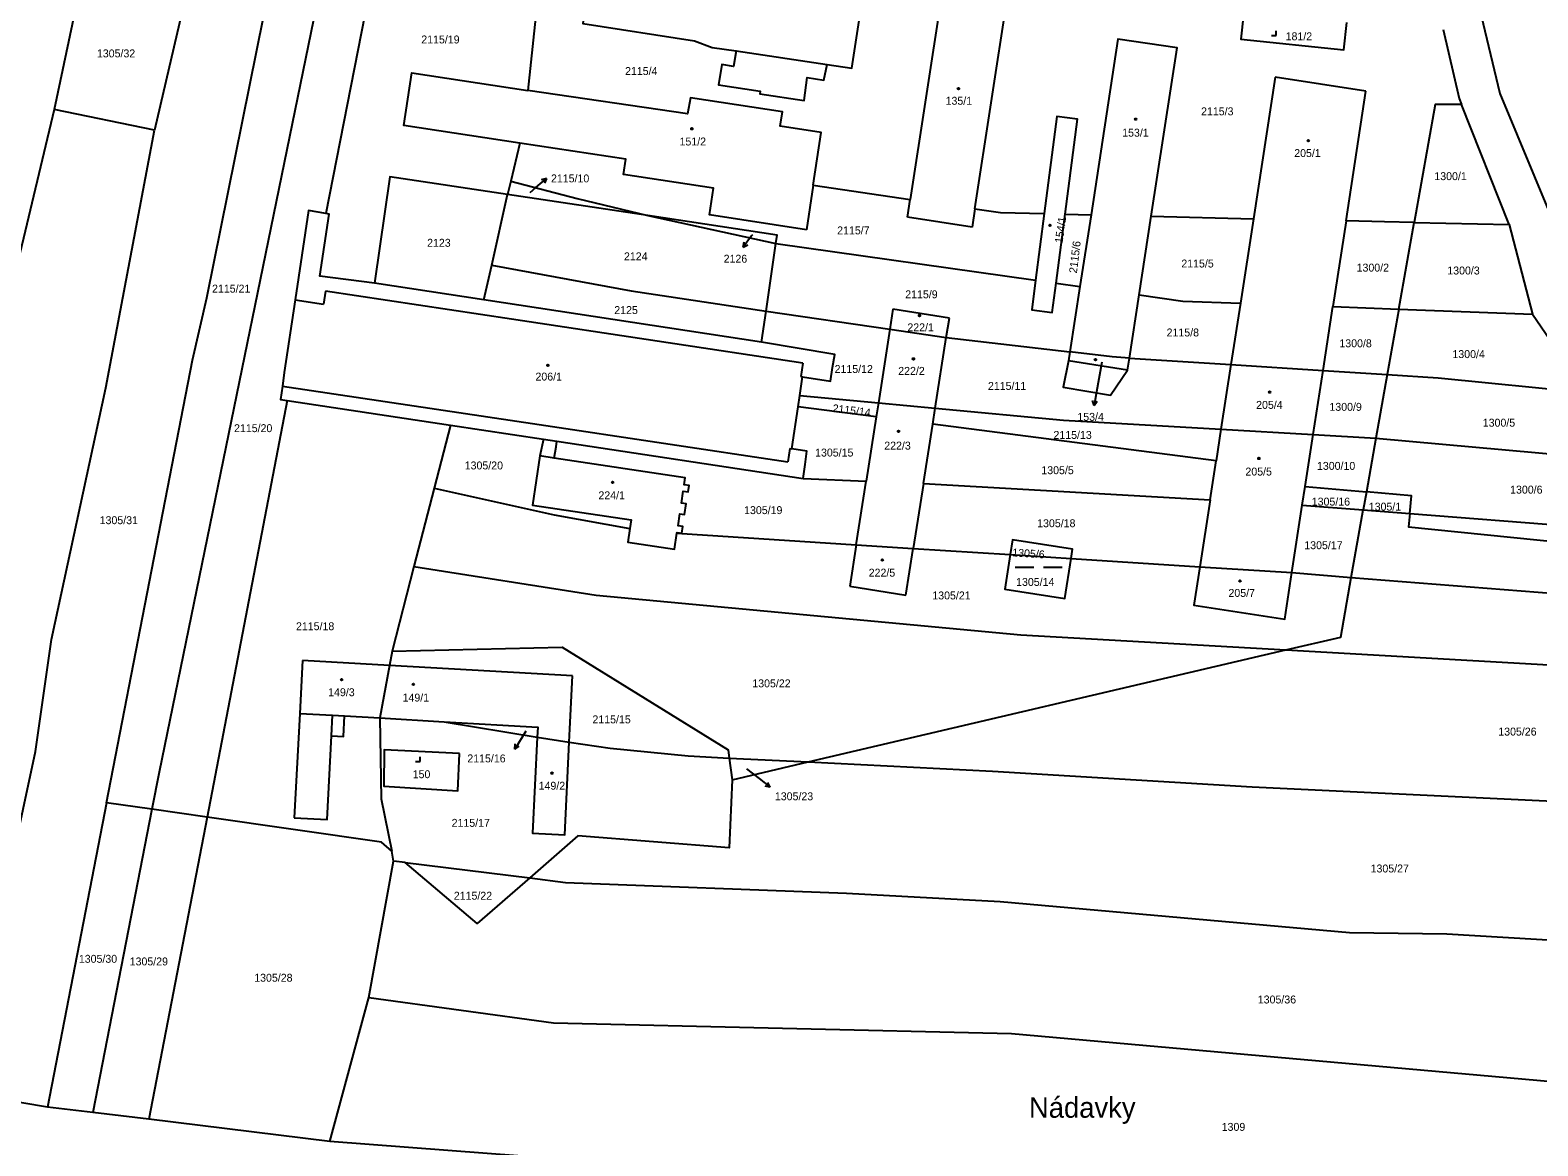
# Model space of a CAD drawing. Extents: x -755528 to -748832, y -1118122 to -1111095.
# Drawn here: x -750683.1 to -750359.5, y -1114035.1 to -1113795.7 of the extents above; entities that cross this region are included whole.
import ezdxf

# ---------------------------------------------------------------- set-up
doc = ezdxf.new("R2010")
doc.units = 0
for name, color, linetype in [('DZ_DO_ostatní', 7, 'Continuous'), ('DZ_DO_PUPFL', 7, 'Continuous'), ('DZ_NAD_ZPF', 7, 'Continuous'), ('legenda barvy', 7, 'Continuous'), ('legenda_text', 7, 'Continuous'), ('TZ_UMVŽST', 7, 'Continuous')]:
    doc.layers.add(name, color=color, linetype=linetype)

msp = doc.modelspace()

# ---------------------------------------------------------------- linework, layer by layer
at = {"layer": 'DZ_DO_ostatní'}
for p, q in [((-750531.57, -1113800.11), (-750512.05, -1113803)), ((-750626.22, -1113853.56), (-750620.16, -1113854.48)), ((-750619.74, -1113851.7), (-750620.16, -1113854.48)), ((-750579.79, -1113857.69), (-750619.74, -1113851.7)), ((-750517.27, -1113867.15), (-750579.79, -1113857.69)), ((-750517.27, -1113867.15), (-750517.71, -1113870)), ((-750447.58, -1113868.63), (-750460.26, -1113866.64)), ((-750517.71, -1113870), (-750517.31, -1113870.06)), ((-750628.95, -1113872.04), (-750573.89, -1113880.32)), ((-750573.89, -1113880.32), (-750520.46, -1113888.32)), ((-750520.05, -1113885.48), (-750520.46, -1113888.32)), ((-750520.05, -1113885.48), (-750519.64, -1113885.55)), ((-750570.61, -1113887.56), (-750573.73, -1113887.05)), ((-750625.24, -1113942.31), (-750618.2, -1113942.71)), ((-750618.43, -1113947.13), (-750618.2, -1113942.71)), ((-750618.2, -1113942.71), (-750615.6, -1113942.86))]:
    msp.add_line(p, q, dxfattribs=at)
at = {"layer": 'DZ_NAD_ZPF'}
for p, q in [((-750605.82, -1113764.21), (-750619.61, -1113835.03)), ((-750572.98, -1113776.85), (-750576.28, -1113808.6)), ((-750671.89, -1113783.99), (-750677.92, -1113812.71)), ((-750649.83, -1113788.82), (-750656.44, -1113817.12)), ((-750487.35, -1113787.31), (-750494.25, -1113831.98)), ((-750480.33, -1113834), (-750473.32, -1113788.44)), ((-750415.89, -1113805.74), (-750420.58, -1113836.13)), ((-750396.42, -1113808.74), (-750415.89, -1113805.74)), ((-750400.7, -1113836.62), (-750396.42, -1113808.74)), ((-750365.72, -1113837.4), (-750375.89, -1113811.64)), ((-750656.44, -1113817.12), (-750677.92, -1113812.71)), ((-750578, -1113819.92), (-750579.97, -1113828.05)), ((-750579.97, -1113828.05), (-750580.67, -1113830.94)), ((-750584.04, -1113846.07), (-750580.67, -1113830.94)), ((-750550.52, -1113835.47), (-750580.67, -1113830.94)), ((-750515.05, -1113828.96), (-750516.48, -1113838.52)), ((-750515.05, -1113828.96), (-750494.25, -1113831.98)), ((-750494.84, -1113835.77), (-750494.25, -1113831.98)), ((-750480.33, -1113834), (-750480.93, -1113837.93)), ((-750465.45, -1113835.03), (-750467.31, -1113849.32)), ((-750550.52, -1113835.47), (-750523.05, -1113841.42)), ((-750480.93, -1113837.93), (-750494.84, -1113835.77)), ((-750462.92, -1113849.94), (-750461, -1113835.14)), ((-750461, -1113835.14), (-750455.43, -1113835.28)), ((-750455.43, -1113835.28), (-750457.8, -1113850.67)), ((-750445.09, -1113852.47), (-750442.49, -1113835.6)), ((-750442.49, -1113835.6), (-750420.58, -1113836.13)), ((-750420.58, -1113836.13), (-750423.37, -1113854.26)), ((-750400.7, -1113836.62), (-750403.53, -1113855)), ((-750389.35, -1113855.53), (-750386.06, -1113836.96)), ((-750386.06, -1113836.96), (-750365.72, -1113837.4)), ((-750365.72, -1113837.4), (-750360.65, -1113856.6)), ((-750525.16, -1113855.97), (-750523.05, -1113841.42)), ((-750523.05, -1113841.42), (-750467.31, -1113849.32)), ((-750585.71, -1113853.56), (-750584.04, -1113846.07)), ((-750585.71, -1113853.56), (-750609.23, -1113849.98)), ((-750462.92, -1113849.94), (-750457.8, -1113850.67)), ((-750457.8, -1113850.67), (-750459.97, -1113864.73)), ((-750526.11, -1113862.62), (-750585.71, -1113853.56)), ((-750447.18, -1113866.03), (-750445.09, -1113852.47)), ((-750423.37, -1113854.26), (-750425.4, -1113867.42)), ((-750526.11, -1113862.62), (-750525.16, -1113855.97)), ((-750525.16, -1113855.97), (-750498.6, -1113859.85)), ((-750497.93, -1113855.58), (-750498.6, -1113859.85)), ((-750485.83, -1113857.5), (-750497.93, -1113855.58)), ((-750486.48, -1113861.61), (-750485.83, -1113857.5)), ((-750405.63, -1113868.69), (-750403.53, -1113855)), ((-750403.53, -1113855), (-750389.35, -1113855.53)), ((-750389.35, -1113855.53), (-750391.84, -1113869.57)), ((-750389.35, -1113855.53), (-750360.65, -1113856.6)), ((-750360.65, -1113856.6), (-750349.25, -1113873.44)), ((-750498.6, -1113859.85), (-750501.06, -1113875.64)), ((-750498.6, -1113859.85), (-750486.48, -1113861.61)), ((-750488.86, -1113876.79), (-750486.48, -1113861.61)), ((-750486.48, -1113861.61), (-750459.97, -1113864.73)), ((-750447.18, -1113866.03), (-750425.4, -1113867.42)), ((-750425.4, -1113867.42), (-750427.54, -1113881.32)), ((-750425.4, -1113867.42), (-750405.63, -1113868.69)), ((-750407.75, -1113882.46), (-750405.63, -1113868.69)), ((-750405.63, -1113868.69), (-750391.84, -1113869.57)), ((-750391.84, -1113869.57), (-750394.27, -1113883.24)), ((-750627.92, -1113875.15), (-750645.14, -1113964.57)), ((-750627.92, -1113875.15), (-750592.92, -1113880.42)), ((-750518.28, -1113876.48), (-750517.91, -1113874.06)), ((-750501.53, -1113878.65), (-750518.28, -1113876.48)), ((-750517.91, -1113874.06), (-750501.06, -1113875.64)), ((-750501.06, -1113875.64), (-750501.53, -1113878.65)), ((-750501.06, -1113875.64), (-750488.86, -1113876.79)), ((-750489.4, -1113880.22), (-750488.86, -1113876.79)), ((-750501.53, -1113878.65), (-750503.69, -1113892.45)), ((-750491.41, -1113892.98), (-750489.4, -1113880.22)), ((-750428.58, -1113888.08), (-750489.4, -1113880.22)), ((-750592.92, -1113880.42), (-750596.4, -1113893.95)), ((-750592.92, -1113880.42), (-750572.92, -1113883.43)), ((-750572.92, -1113883.43), (-750570.04, -1113883.89)), ((-750427.54, -1113881.32), (-750428.58, -1113888.08)), ((-750427.54, -1113881.32), (-750407.75, -1113882.46)), ((-750409.46, -1113893.59), (-750407.75, -1113882.46)), ((-750407.75, -1113882.46), (-750394.27, -1113883.24)), ((-750394.27, -1113883.24), (-750396.31, -1113894.76)), ((-750394.27, -1113883.24), (-750331.5, -1113888.93)), ((-750570.04, -1113883.89), (-750517.22, -1113891.86)), ((-750429.87, -1113896.48), (-750428.58, -1113888.08)), ((-750517.22, -1113891.86), (-750503.69, -1113892.45)), ((-750505.82, -1113906.11), (-750503.69, -1113892.45)), ((-750491.41, -1113892.98), (-750493.6, -1113906.89)), ((-750491.41, -1113892.98), (-750429.87, -1113896.48)), ((-750596.4, -1113893.95), (-750600.73, -1113910.8)), ((-750429.87, -1113896.48), (-750432.08, -1113910.83)), ((-750410.08, -1113897.6), (-750409.46, -1113893.59)), ((-750409.46, -1113893.59), (-750396.31, -1113894.76)), ((-750396.31, -1113894.76), (-750396.99, -1113898.61)), ((-750412.3, -1113912.1), (-750410.08, -1113897.6)), ((-750410.08, -1113897.6), (-750396.99, -1113898.61)), ((-750399.57, -1113913.11), (-750396.99, -1113898.61)), ((-750396.99, -1113898.61), (-750386.99, -1113899.39)), ((-750386.99, -1113899.39), (-750309.59, -1113905.41)), ((-750544.28, -1113903.64), (-750505.82, -1113906.11)), ((-750505.82, -1113906.11), (-750507.21, -1113915.01)), ((-750505.82, -1113906.11), (-750493.6, -1113906.89)), ((-750495.17, -1113916.92), (-750493.6, -1113906.89)), ((-750493.6, -1113906.89), (-750472.79, -1113908.22)), ((-750472.79, -1113908.22), (-750459.71, -1113909.06)), ((-750459.71, -1113909.06), (-750432.08, -1113910.83)), ((-750600.73, -1113910.8), (-750605.39, -1113928.92)), ((-750432.08, -1113910.83), (-750412.3, -1113912.1)), ((-750412.3, -1113912.1), (-750399.57, -1113913.11)), ((-750507.21, -1113915.01), (-750495.17, -1113916.92)), ((-750399.57, -1113913.11), (-750290.98, -1113921.75)), ((-750516.14, -1113952.73), (-750413.63, -1113928.68)), ((-750413.63, -1113928.68), (-750275.6, -1113936.54)), ((-750605.96, -1113932), (-750624.64, -1113930.95)), ((-750605.96, -1113932), (-750608.04, -1113943.29)), ((-750605.39, -1113928.92), (-750605.96, -1113932)), ((-750566.67, -1113934.23), (-750605.96, -1113932)), ((-750567.26, -1113945.63), (-750566.67, -1113934.23)), ((-750608.04, -1113943.29), (-750594.23, -1113944.09)), ((-750594.23, -1113944.09), (-750574.26, -1113947.42)), ((-750574.26, -1113947.42), (-750567.4, -1113948.45)), ((-750567.4, -1113948.45), (-750567.26, -1113945.63)), ((-750533.06, -1113951.88), (-750516.14, -1113952.73)), ((-750533.06, -1113951.88), (-750532.46, -1113956.56)), ((-750532.46, -1113956.56), (-750516.14, -1113952.73)), ((-750666.69, -1113961.47), (-750679.36, -1114026.8)), ((-750656.98, -1113962.87), (-750669.61, -1114027.94)), ((-750656.98, -1113962.87), (-750666.69, -1113961.47)), ((-750645.14, -1113964.57), (-750656.98, -1113962.87)), ((-750645.14, -1113964.57), (-750657.61, -1114029.36)), ((-750610.4, -1114003.29), (-750605.15, -1113973.99)), ((-750605.15, -1113973.99), (-750605.46, -1113971.88)), ((-750602.6, -1113974.3), (-750605.15, -1113973.99)), ((-750602.6, -1113974.3), (-750575.88, -1113977.58)), ((-750618.81, -1114034.16), (-750610.4, -1114003.29)), ((-750679.36, -1114026.8), (-750697.69, -1114023.72)), ((-750669.61, -1114027.94), (-750679.36, -1114026.8)), ((-750657.61, -1114029.36), (-750669.61, -1114027.94)), ((-750618.81, -1114034.16), (-750657.61, -1114029.36))]:
    msp.add_line(p, q, dxfattribs=at)
for points in [[(-750394.18, -1113687.07), (-750374.25, -1113712.84), (-750364.39, -1113734.2), (-750362.92, -1113755.97), (-750369.18, -1113776.02), (-750371.71, -1113792.51), (-750367.7, -1113809.24), (-750356.56, -1113836.11), (-750350.79, -1113846.38)], [(-750616.02, -1113762.71), (-750655.44, -1113954.92), (-750656.98, -1113962.87)], [(-750545.29, -1113783.44), (-750562.36, -1113780.95), (-750564.5, -1113794.22), (-750540.53, -1113797.95), (-750536.71, -1113799.35), (-750531.57, -1113800.11), (-750532.13, -1113803.44), (-750534.69, -1113803.06), (-750535.35, -1113807.43), (-750526.44, -1113808.76), (-750526.5, -1113809.3), (-750516.99, -1113810.76), (-750516.33, -1113805.85), (-750512.74, -1113806.39), (-750512.05, -1113803), (-750506.74, -1113803.79), (-750504.44, -1113788.89), (-750511.58, -1113787.57), (-750511.24, -1113785.44)], [(-750666.69, -1113961.47), (-750648.27, -1113866.49), (-750645.15, -1113853.14), (-750632.98, -1113792.5)], [(-750422.71, -1113792.34), (-750423.28, -1113797.57), (-750401.17, -1113799.91), (-750400.54, -1113793.99)], [(-750379.85, -1113795.53), (-750376.41, -1113810.33), (-750375.89, -1113811.64)], [(-750442.49, -1113835.6), (-750436.94, -1113799.49), (-750449.64, -1113797.58), (-750455.43, -1113835.28)], [(-750578, -1113819.92), (-750602.88, -1113816.13), (-750601.2, -1113804.85), (-750576.28, -1113808.6)], [(-750515.05, -1113828.96), (-750513.35, -1113817.62), (-750522.12, -1113816.26), (-750521.67, -1113813.19), (-750541.39, -1113810.16), (-750541.99, -1113813.59), (-750576.28, -1113808.6)], [(-750375.89, -1113811.64), (-750381.57, -1113811.64), (-750386.06, -1113836.96)], [(-750677.92, -1113812.71), (-750688.59, -1113857.37), (-750702.1, -1113930.36), (-750719.33, -1114017.54)], [(-750461, -1113835.14), (-750458.36, -1113814.78), (-750462.75, -1113814.21), (-750465.45, -1113835.03)], [(-750697.69, -1114023.72), (-750681.93, -1113950.45), (-750678.53, -1113926.42), (-750666.87, -1113872.44), (-750656.44, -1113817.12)], [(-750516.48, -1113838.52), (-750537.28, -1113835.31), (-750536.46, -1113829.59), (-750555.75, -1113826.67), (-750555.25, -1113823.35), (-750578, -1113819.92)], [(-750580.67, -1113830.94), (-750605.88, -1113827.15), (-750609.23, -1113849.98)], [(-750579.97, -1113828.05), (-750565.67, -1113831.82), (-750550.52, -1113835.47)], [(-750619.61, -1113835.03), (-750623.39, -1113834.4), (-750626.22, -1113853.56), (-750628.57, -1113869.14), (-750628.95, -1113872.04), (-750629.4, -1113874.92), (-750627.92, -1113875.15)], [(-750609.23, -1113849.98), (-750620.95, -1113848.49), (-750618.94, -1113835.14), (-750619.61, -1113835.03)], [(-750480.33, -1113834), (-750474.83, -1113834.8), (-750465.45, -1113835.03)], [(-750523.05, -1113841.42), (-750522.8, -1113839.63), (-750550.52, -1113835.47)], [(-750386.06, -1113836.96), (-750392.45, -1113836.82), (-750400.7, -1113836.62)], [(-750584.04, -1113846.07), (-750554.14, -1113851.63), (-750525.16, -1113855.97)], [(-750467.31, -1113849.32), (-750468.13, -1113855.68), (-750463.74, -1113856.25), (-750462.92, -1113849.94)], [(-750445.09, -1113852.47), (-750435.75, -1113853.8), (-750423.37, -1113854.26)], [(-750517.91, -1113874.06), (-750517.31, -1113870.06), (-750511.37, -1113870.98), (-750510.89, -1113868.04), (-750510.44, -1113865.31), (-750526.11, -1113862.62)], [(-750459.97, -1113864.73), (-750460.26, -1113866.64), (-750461.43, -1113872.32), (-750451.23, -1113874.02), (-750447.58, -1113868.63), (-750447.18, -1113866.03)], [(-750447.18, -1113866.03), (-750450.92, -1113865.79), (-750459.97, -1113864.73)], [(-750391.84, -1113869.57), (-750380.96, -1113870.27), (-750349.25, -1113873.44)], [(-750517.22, -1113891.86), (-750516.79, -1113888.85), (-750516.44, -1113886), (-750519.64, -1113885.55), (-750518.28, -1113876.48)], [(-750488.86, -1113876.79), (-750461.36, -1113879.38), (-750427.54, -1113881.32)], [(-750572.92, -1113883.43), (-750573.73, -1113887.05), (-750575.3, -1113897.58), (-750554.12, -1113900.77), (-750554.4, -1113902.61)], [(-750544.28, -1113903.64), (-750544.26, -1113903.49), (-750543.27, -1113903.64), (-750543.06, -1113902.22), (-750544.05, -1113902.08), (-750543.66, -1113899.48), (-750542.67, -1113899.62), (-750542.3, -1113897.31), (-750543.31, -1113897.16), (-750542.92, -1113894.58), (-750541.87, -1113894.74), (-750541.68, -1113893.39), (-750542.73, -1113893.25), (-750542.5, -1113891.77), (-750570.61, -1113887.56), (-750570.22, -1113885.09), (-750570.04, -1113883.89)], [(-750596.4, -1113893.95), (-750570.62, -1113899.71), (-750554.4, -1113902.61)], [(-750386.99, -1113899.39), (-750386.63, -1113895.63), (-750396.31, -1113894.76)], [(-750386.99, -1113899.39), (-750387.26, -1113902.24), (-750303.26, -1113910.79)], [(-750554.4, -1113902.61), (-750554.83, -1113905.55), (-750544.83, -1113907.07), (-750544.28, -1113903.64)], [(-750459.71, -1113909.06), (-750459.4, -1113907.06), (-750472.31, -1113905.08), (-750472.79, -1113908.22)], [(-750472.79, -1113908.22), (-750473.93, -1113915.67), (-750461.02, -1113917.65), (-750459.71, -1113909.06)], [(-750600.73, -1113910.8), (-750561.61, -1113916.9), (-750470.46, -1113925.45), (-750413.63, -1113928.68)], [(-750432.08, -1113910.83), (-750433.35, -1113919.06), (-750413.84, -1113922.11), (-750412.3, -1113912.1)], [(-750413.63, -1113928.68), (-750401.84, -1113925.92), (-750399.57, -1113913.11)], [(-750605.39, -1113928.92), (-750568.95, -1113928.08), (-750533.29, -1113950.09), (-750533.06, -1113951.88)], [(-750624.64, -1113930.95), (-750625.24, -1113942.31), (-750626.44, -1113964.69)], [(-750626.44, -1113964.69), (-750619.38, -1113965.06), (-750618.43, -1113947.13), (-750615.83, -1113947.26), (-750615.6, -1113942.86), (-750608.04, -1113943.29)], [(-750608.04, -1113943.29), (-750607.8, -1113960.65), (-750605.46, -1113971.88)], [(-750594.23, -1113944.09), (-750574.15, -1113945.24), (-750574.26, -1113947.42)], [(-750574.26, -1113947.42), (-750575.27, -1113968.01), (-750568.38, -1113968.35), (-750567.4, -1113948.45)], [(-750590.93, -1113950.89), (-750607.15, -1113950.09), (-750607.22, -1113957.94), (-750591.33, -1113958.9), (-750590.93, -1113950.89)], [(-750567.4, -1113948.45), (-750558.59, -1113949.77), (-750541.9, -1113951.43), (-750533.06, -1113951.88)], [(-750516.14, -1113952.73), (-750476.6, -1113954.73), (-750420.88, -1113958.1), (-750348.73, -1113961.53), (-750251.84, -1113969.47)], [(-750532.46, -1113956.56), (-750533.11, -1113971.18), (-750565.53, -1113968.58), (-750575.88, -1113977.58)], [(-750605.46, -1113971.88), (-750607.73, -1113969.96), (-750645.14, -1113964.57)], [(-750575.88, -1113977.58), (-750587.14, -1113987.37), (-750602.6, -1113974.3)], [(-750575.88, -1113977.58), (-750568.19, -1113978.59), (-750507.93, -1113980.91), (-750474.94, -1113982.65), (-750399.94, -1113989.32), (-750379.08, -1113989.65), (-750291.29, -1113994.84), (-750235.94, -1114002.32)], [(-750610.4, -1114003.29), (-750570.76, -1114008.72), (-750472.46, -1114010.98), (-750312.27, -1114025.25), (-750224.9, -1114030.76)], [(-750515.41, -1114040.75), (-750552.21, -1114039.28), (-750618.81, -1114034.16)]]:
    msp.add_lwpolyline(points, dxfattribs=at)
at = {"layer": 'legenda barvy'}
for p, q in [((-750574.58, -1113829.45), (-750572.315, -1113827.481)), ((-750572.315, -1113827.481), (-750573.399, -1113827.76)), ((-750572.315, -1113827.481), (-750572.742, -1113828.516)), ((-750575.8, -1113830.52), (-750574.58, -1113829.45)), ((-750528.26, -1113839.83), (-750530.066, -1113842.227)), ((-750530.066, -1113842.227), (-750529.863, -1113841.126)), ((-750528.09, -1113839.6), (-750528.26, -1113839.83)), ((-750530.066, -1113842.227), (-750529.063, -1113841.728)), ((-750453.12, -1113866.9), (-750454.25, -1113873.27)), ((-750454.25, -1113873.27), (-750454.771, -1113876.225)), ((-750454.771, -1113876.225), (-750455.09, -1113875.152)), ((-750454.771, -1113876.225), (-750454.104, -1113875.326)), ((-750577.51, -1113947.41), (-750579.1, -1113949.955)), ((-750576.73, -1113946.14), (-750577.51, -1113947.41)), ((-750579.1, -1113949.955), (-750578.994, -1113948.84)), ((-750579.1, -1113949.955), (-750578.145, -1113949.371)), ((-750529.36, -1113954.18), (-750526.65, -1113956.27)), ((-750526.65, -1113956.27), (-750524.285, -1113958.118)), ((-750524.285, -1113958.118), (-750525.383, -1113957.896)), ((-750524.285, -1113958.118), (-750524.766, -1113957.106))]:
    msp.add_line(p, q, dxfattribs=at)
at = {"layer": 'legenda_text'}
for centre in [(-750483.8768, -1113808.2292), (-750445.8268, -1113814.7692), (-750541.0968, -1113816.8292), (-750408.8068, -1113819.3692), (-750464.2368, -1113837.5392), (-750492.2368, -1113856.9192), (-750493.5368, -1113866.2192), (-750454.4768, -1113866.3892), (-750571.9868, -1113867.5892), (-750417.0768, -1113873.3492), (-750496.7368, -1113881.7692), (-750419.4068, -1113887.5892), (-750558.0868, -1113892.6992), (-750500.2168, -1113909.3692), (-750423.4668, -1113913.8792), (-750616.2468, -1113935.0592), (-750600.8468, -1113936.0492), (-750571.0868, -1113955.1292)]:
    msp.add_circle(centre, 0.175, dxfattribs=at)
at = {"layer": 'TZ_UMVŽST'}
for p, q in [((-750415.72, -1113796.79), (-750415.72, -1113795.79)), ((-750416.721, -1113796.79), (-750415.72, -1113796.79)), ((-750471.688, -1113910.95), (-750467.668, -1113910.95)), ((-750465.658, -1113910.95), (-750461.638, -1113910.95)), ((-750600.421, -1113952.66), (-750599.42, -1113952.66)), ((-750599.42, -1113952.66), (-750599.42, -1113951.66))]:
    msp.add_line(p, q, dxfattribs=at)

# ---------------------------------------------------------------- texts
at = {"layer": 'DZ_DO_PUPFL'}
for s, p in [('181/2', (-750413.66, -1113797.83)), ('2115/19', (-750599.156, -1113798.51)), ('1305/32', (-750668.766, -1113801.5)), ('2115/4', (-750555.427, -1113805.29)), ('135/1', (-750486.64, -1113811.67)), ('2115/3', (-750431.807, -1113813.94)), ('151/2', (-750543.73, -1113820.41)), ('153/1', (-750448.74, -1113818.52)), ('205/1', (-750411.82, -1113822.89)), ('2115/10', (-750571.32, -1113828.33)), ('1300/1', (-750381.747, -1113827.85)), ('2115/7', (-750509.907, -1113839.49)), ('2123', (-750597.91, -1113842.15)), ('2124', (-750555.66, -1113845.06)), ('2126', (-750534.268, -1113845.568)), ('2115/5', (-750436.047, -1113846.6)), ('1300/2', (-750398.427, -1113847.48)), ('1300/3', (-750378.967, -1113848.1)), ('2115/21', (-750644.056, -1113851.99)), ('2115/9', (-750495.297, -1113853.21)), ('2125', (-750557.74, -1113856.59)), ('222/1', (-750494.84, -1113860.3)), ('2115/8', (-750439.207, -1113861.4)), ('1300/8', (-750402.127, -1113863.72)), ('1300/4', (-750377.867, -1113866.04)), ('206/1', (-750574.65, -1113870.87)), ('2115/12', (-750510.456, -1113869.24)), ('222/2', (-750496.8, -1113869.64)), ('2115/11', (-750477.546, -1113872.87)), ('205/4', (-750419.99, -1113876.94)), ('1300/9', (-750404.267, -1113877.36)), ('2115/20', (-750639.336, -1113881.94)), ('153/4', (-750458.358, -1113879.51)), ('1300/5', (-750371.357, -1113880.76)), ('2115/13', (-750463.486, -1113883.39)), ('1305/15', (-750514.636, -1113887.17)), ('222/3', (-750499.8, -1113885.68)), ('1305/20', (-750589.836, -1113889.94)), ('1305/5', (-750466.087, -1113890.96)), ('205/5', (-750422.29, -1113891.25)), ('1300/10', (-750406.936, -1113890.03)), ('224/1', (-750561.14, -1113896.35)), ('1305/16', (-750408.056, -1113897.7)), ('1300/6', (-750365.487, -1113895.13)), ('1305/19', (-750529.876, -1113899.53)), ('1305/1', (-750395.817, -1113898.78)), ('1305/31', (-750668.176, -1113901.69)), ('1305/18', (-750466.986, -1113902.34)), ('1305/17', (-750409.656, -1113907.06)), ('222/5', (-750503.14, -1113912.95)), ('1305/14', (-750471.506, -1113914.94)), ('205/7', (-750425.93, -1113917.3)), ('1305/21', (-750489.486, -1113917.84)), ('2115/18', (-750626.046, -1113924.45)), ('1305/22', (-750528.116, -1113936.71)), ('149/3', (-750619.14, -1113938.61)), ('149/1', (-750603.17, -1113939.76)), ('2115/15', (-750562.426, -1113944.44)), ('1305/26', (-750368.026, -1113947.06)), ('2115/16', (-750589.273, -1113952.818)), ('150', (-750601, -1113956.21)), ('149/2', (-750573.97, -1113958.68)), ('1305/23', (-750523.27, -1113960.948)), ('2115/17', (-750592.646, -1113966.65)), ('1305/27', (-750395.426, -1113976.44)), ('2115/22', (-750592.176, -1113982.29)), ('1305/30', (-750672.646, -1113995.83)), ('1305/29', (-750661.736, -1113996.39)), ('1305/28', (-750635.006, -1113999.89)), ('1305/36', (-750419.636, -1114004.56)), ('1309', (-750427.384, -1114031.9))]:
    msp.add_text(s, height=1.7, dxfattribs=at).set_placement(p)
for s, rotation, p in [('154/1', 82, (-750461.538, -1113841.458)), ('2115/6', 83, (-750458.467, -1113847.911)), ('2115/14', 353, (-750510.976, -1113877.613)), ('1305/6', 356, (-750472.377, -1113908.582))]:
    msp.add_text(s, height=1.7, rotation=rotation, dxfattribs=at).set_placement(p)
at = {"layer": 'legenda barvy'}
msp.add_text('Nádavky', height=4.4, dxfattribs=at).set_placement((-750468.752, -1114029.09))

doc.saveas('drawing.dxf')
